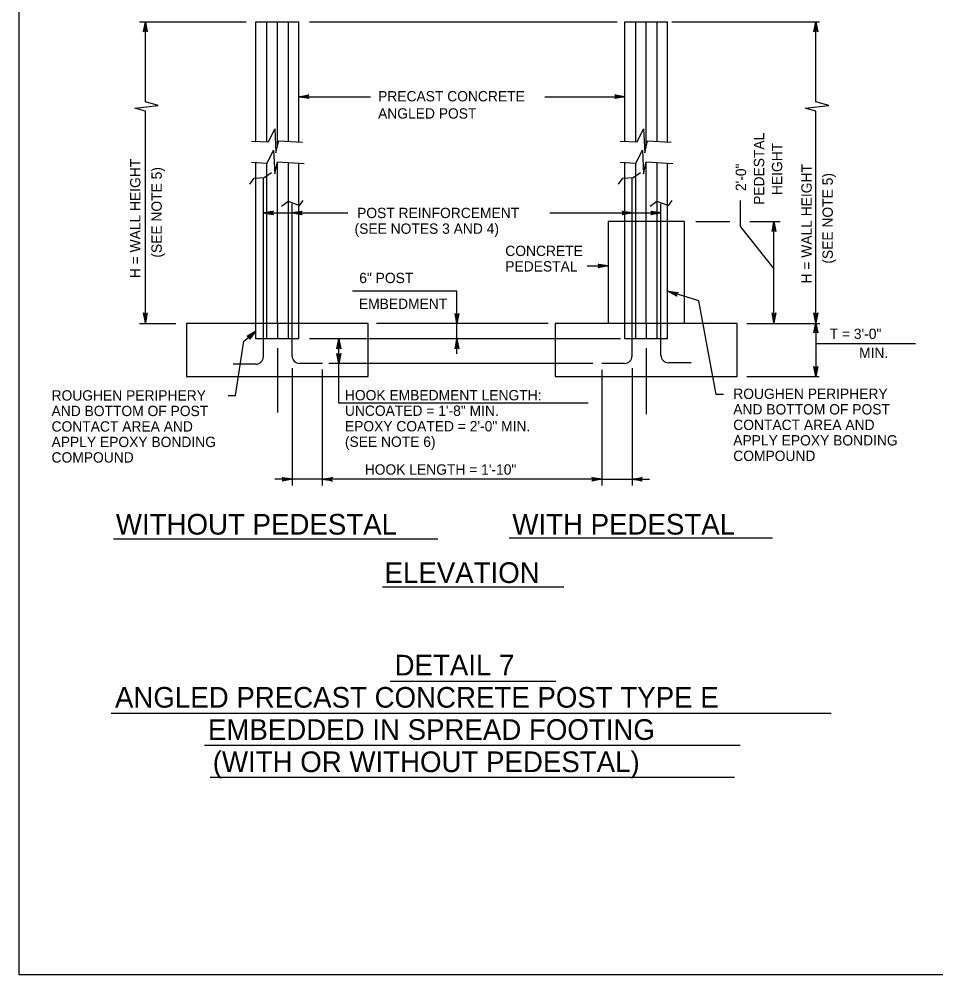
# Model space of a CAD drawing. Extents: x 3351 to 8430, y -3586 to 1457.
# Drawn here: x 5483.3 to 5755.8, y -2977.3 to -2693.1 of the extents above; entities that cross this region are included whole.
import ezdxf

# ---------------------------------------------------------------- set-up
doc = ezdxf.new("R2010")
doc.units = 0
doc.layers.add('1', color=7, linetype='Continuous')
doc.layers.add('2', color=7, linetype='Continuous')

msp = doc.modelspace()

# ---------------------------------------------------------------- linework, layer by layer
at = {"layer": '1'}
for p, q in [((5519.11, -2693.93), (5550.81, -2693.93)), ((5520.86, -2717.76), (5520.86, -2693.93)), ((5553.72, -2693.93), (5566.47, -2693.93)), ((5553.72, -2729.47), (5553.72, -2693.93)), ((5556.89, -2693.93), (5556.89, -2729.62)), ((5560.09, -2731.02), (5560.09, -2693.93)), ((5563.29, -2693.93), (5563.29, -2729.48)), ((5566.47, -2729.66), (5566.47, -2693.93)), ((5569.62, -2693.93), (5661.03, -2693.93)), ((5663.31, -2693.93), (5676.06, -2693.93)), ((5663.31, -2729.46), (5663.31, -2693.93)), ((5666.49, -2693.93), (5666.49, -2729.62)), ((5669.69, -2731.02), (5669.69, -2693.93)), ((5672.89, -2693.93), (5672.89, -2729.48)), ((5676.06, -2729.66), (5676.06, -2693.93)), ((5677.32, -2693.93), (5721.19, -2693.93)), ((5720.1, -2717.76), (5720.1, -2693.93)), ((5566.47, -2716.2), (5587.76, -2716.2)), ((5639.6, -2716.2), (5663.31, -2716.2)), ((5520.86, -2783.47), (5520.86, -2720.46)), ((5720.1, -2783.47), (5720.1, -2720.46)), ((5553.72, -2783.66), (5553.72, -2735.78)), ((5556.89, -2735.94), (5556.89, -2788.16)), ((5560.09, -2783.66), (5560.09, -2735.72)), ((5563.29, -2735.8), (5563.29, -2788.16)), ((5566.47, -2783.66), (5566.47, -2735.97)), ((5663.31, -2753.31), (5663.31, -2735.78)), ((5666.49, -2735.94), (5666.49, -2788.16)), ((5669.69, -2783.66), (5669.69, -2735.72)), ((5672.89, -2735.8), (5672.89, -2788.16)), ((5676.06, -2753.31), (5676.06, -2735.97)), ((5556.2, -2740.26), (5558.36, -2738.75)), ((5665.8, -2740.26), (5667.96, -2738.75)), ((5551.89, -2742.2), (5553.18, -2740.47)), ((5553.18, -2740.47), (5556.2, -2740.26)), ((5555.92, -2793.49), (5555.92, -2740.26)), ((5661.49, -2742.2), (5662.78, -2740.47)), ((5662.78, -2740.47), (5665.8, -2740.26)), ((5665.52, -2793.27), (5665.52, -2740.26)), ((5561.31, -2748.78), (5563.25, -2747.27)), ((5563.25, -2747.27), (5566.7, -2748.56)), ((5566.7, -2748.56), (5567.78, -2747.05)), ((5670.9, -2748.78), (5672.85, -2747.27)), ((5672.85, -2747.27), (5676.3, -2748.56)), ((5676.3, -2748.56), (5677.37, -2747.05)), ((5697.74, -2754.9), (5697.74, -2747.02)), ((5564.46, -2793.27), (5564.46, -2748.03)), ((5674.06, -2793.06), (5674.06, -2748.03)), ((5555.92, -2750.78), (5581.07, -2750.78)), ((5641.09, -2750.78), (5674.06, -2750.78)), ((5658.39, -2753.31), (5658.39, -2783.66)), ((5680.99, -2753.31), (5658.39, -2753.31)), ((5663.31, -2788.16), (5663.31, -2753.31)), ((5676.06, -2788.16), (5676.06, -2753.31)), ((5680.99, -2753.31), (5680.99, -2783.66)), ((5684.43, -2753.31), (5694.59, -2753.31)), ((5700.5, -2753.31), (5709.54, -2753.31)), ((5707.65, -2783.47), (5707.65, -2753.31)), ((5697.74, -2754.9), (5707.65, -2767.42)), ((5652.11, -2766.54), (5658.39, -2766.54)), ((5582.42, -2773.91), (5613.44, -2773.91)), ((5613.44, -2783.66), (5613.44, -2773.91)), ((5519.11, -2783.66), (5529.87, -2783.66)), ((5566.86, -2783.66), (5533.09, -2783.66)), ((5533.09, -2783.66), (5533.09, -2799.41)), ((5553.72, -2788.16), (5553.72, -2783.66)), ((5560.09, -2783.66), (5560.09, -2788.16)), ((5566.47, -2788.16), (5566.47, -2783.66)), ((5587.09, -2783.66), (5566.47, -2783.66)), ((5587.09, -2799.41), (5587.09, -2783.66)), ((5640.56, -2783.66), (5589.57, -2783.66)), ((5613.44, -2787.8), (5613.44, -2783.66)), ((5676.45, -2783.66), (5642.69, -2783.66)), ((5642.69, -2783.66), (5642.69, -2799.41)), ((5669.69, -2783.66), (5669.69, -2788.16)), ((5696.69, -2783.66), (5676.06, -2783.66)), ((5696.69, -2799.41), (5696.69, -2783.66)), ((5699.57, -2783.66), (5721.3, -2783.66)), ((5720.1, -2783.47), (5720.1, -2799.41)), ((5566.47, -2788.16), (5553.72, -2788.16)), ((5662.02, -2788.16), (5569.62, -2788.16)), ((5578.36, -2795.62), (5578.36, -2788.08)), ((5613.44, -2792.63), (5613.44, -2787.8)), ((5676.06, -2788.16), (5663.31, -2788.16)), ((5720.1, -2789.59), (5749.7, -2789.59)), ((5560.09, -2791), (5560.09, -2810.13)), ((5669.69, -2791), (5669.69, -2810.61)), ((5553.67, -2795.74), (5546.92, -2795.74)), ((5573.46, -2795.52), (5566.71, -2795.52)), ((5653.81, -2795.52), (5575.39, -2795.52)), ((5578.36, -2807.31), (5578.36, -2795.62)), ((5663.27, -2795.52), (5656.52, -2795.52)), ((5683.06, -2795.31), (5676.31, -2795.31)), ((5564.46, -2796.92), (5564.46, -2831.79)), ((5573.44, -2797.35), (5573.44, -2831.79)), ((5656.53, -2797.45), (5656.53, -2831.79)), ((5665.52, -2796.92), (5665.52, -2831.79)), ((5533.09, -2799.41), (5587.09, -2799.41)), ((5642.69, -2799.41), (5696.69, -2799.41)), ((5699.57, -2799.41), (5721.1, -2799.41)), ((5652.48, -2807.31), (5578.36, -2807.31)), ((5573.44, -2829.94), (5559.3, -2829.94)), ((5656.53, -2829.94), (5573.44, -2829.94)), ((5656.53, -2829.94), (5670.68, -2829.94)), ((5628.93, -2847.35), (5707.19, -2847.35)), ((5511.41, -2847.68), (5607.75, -2847.68)), ((5591.34, -2861.96), (5645.23, -2861.96)), ((5593.57, -2889.96), (5642.85, -2889.96)), ((5510.73, -2899.47), (5724.66, -2899.47)), ((5538.48, -2908.98), (5697.63, -2908.98)), ((5540.14, -2918.49), (5695.97, -2918.49))]:
    msp.add_line(p, q, dxfattribs=at)
for points in [[(5520.86, -2693.93), (5521.42, -2696.91), (5521.26, -2696.68), (5521.06, -2696.57), (5520.86, -2696.53), (5520.66, -2696.57), (5520.46, -2696.68), (5520.3, -2696.91), (5520.86, -2693.93), (5520.46, -2696.68), (5520.66, -2696.57), (5520.86, -2693.93), (5520.86, -2696.53), (5521.06, -2696.57), (5520.86, -2693.93), (5521.26, -2696.68)], [(5720.1, -2693.93), (5720.66, -2696.91), (5720.5, -2696.68), (5720.3, -2696.57), (5720.1, -2696.53), (5719.9, -2696.57), (5719.7, -2696.68), (5719.54, -2696.91), (5720.1, -2693.93), (5719.7, -2696.68), (5719.9, -2696.57), (5720.1, -2693.93), (5720.1, -2696.53), (5720.3, -2696.57), (5720.1, -2693.93), (5720.5, -2696.68)], [(5566.47, -2716.2), (5569.45, -2715.64), (5569.22, -2715.79), (5569.1, -2715.99), (5569.07, -2716.2), (5569.1, -2716.39), (5569.22, -2716.59), (5569.45, -2716.75), (5566.47, -2716.2), (5569.22, -2716.59), (5569.1, -2716.39), (5566.47, -2716.2), (5569.07, -2716.2), (5569.1, -2715.99), (5566.47, -2716.2), (5569.22, -2715.79)], [(5663.31, -2716.2), (5660.33, -2716.75), (5660.56, -2716.59), (5660.68, -2716.39), (5660.71, -2716.2), (5660.68, -2715.99), (5660.56, -2715.79), (5660.33, -2715.64), (5663.31, -2716.2), (5660.56, -2715.79), (5660.68, -2715.99), (5663.31, -2716.2), (5660.71, -2716.2), (5660.68, -2716.39), (5663.31, -2716.2), (5660.56, -2716.59)], [(5520.86, -2720.46), (5517.72, -2719.59), (5524.7, -2718.84), (5520.86, -2717.76)], [(5720.1, -2720.46), (5716.96, -2719.59), (5723.94, -2718.84), (5720.1, -2717.76)], [(5552.38, -2729.4), (5557.41, -2729.65), (5559.35, -2725.78), (5559.67, -2732.88), (5560.48, -2729.33), (5567.52, -2729.72)], [(5661.97, -2729.4), (5667.01, -2729.65), (5668.94, -2725.78), (5669.27, -2732.88), (5670.07, -2729.33), (5677.11, -2729.72)], [(5552.37, -2735.71), (5557.05, -2735.94), (5558.98, -2732.07), (5559.31, -2739.17), (5560.11, -2735.62), (5568.02, -2736.06)], [(5661.97, -2735.71), (5666.64, -2735.94), (5668.58, -2732.07), (5668.9, -2739.17), (5669.71, -2735.62), (5677.61, -2736.06)], [(5555.92, -2750.78), (5558.9, -2750.22), (5558.79, -2750.3), (5558.67, -2750.38), (5558.61, -2750.48), (5558.55, -2750.58), (5558.54, -2750.68), (5558.52, -2750.78), (5558.54, -2750.88), (5558.55, -2750.98), (5558.61, -2751.08), (5558.67, -2751.18), (5558.79, -2751.26), (5558.9, -2751.34), (5555.92, -2750.78), (5558.79, -2751.26), (5558.67, -2751.18), (5555.92, -2750.78), (5558.61, -2751.08), (5558.55, -2750.98), (5555.92, -2750.78), (5558.54, -2750.88), (5558.52, -2750.78), (5555.92, -2750.78), (5558.54, -2750.68), (5558.55, -2750.58), (5555.92, -2750.78), (5558.61, -2750.48), (5558.67, -2750.38), (5555.92, -2750.78), (5558.79, -2750.3)], [(5564.46, -2750.78), (5567.44, -2750.22), (5567.33, -2750.3), (5567.21, -2750.38), (5567.15, -2750.48), (5567.09, -2750.58), (5567.08, -2750.68), (5567.06, -2750.78), (5567.08, -2750.88), (5567.09, -2750.98), (5567.15, -2751.08), (5567.21, -2751.18), (5567.33, -2751.26), (5567.44, -2751.34), (5564.46, -2750.78), (5567.33, -2751.26), (5567.21, -2751.18), (5564.46, -2750.78), (5567.15, -2751.08), (5567.09, -2750.98), (5564.46, -2750.78), (5567.08, -2750.88), (5567.06, -2750.78), (5564.46, -2750.78), (5567.08, -2750.68), (5567.09, -2750.58), (5564.46, -2750.78), (5567.15, -2750.48), (5567.21, -2750.38), (5564.46, -2750.78), (5567.33, -2750.3)], [(5665.52, -2750.78), (5662.53, -2751.34), (5662.65, -2751.26), (5662.76, -2751.18), (5662.82, -2751.08), (5662.88, -2750.98), (5662.9, -2750.88), (5662.92, -2750.78), (5662.9, -2750.68), (5662.88, -2750.58), (5662.82, -2750.48), (5662.76, -2750.38), (5662.65, -2750.3), (5662.53, -2750.22), (5665.52, -2750.78), (5662.65, -2750.3), (5662.76, -2750.38), (5665.52, -2750.78), (5662.82, -2750.48), (5662.88, -2750.58), (5665.52, -2750.78), (5662.9, -2750.68), (5662.92, -2750.78), (5665.52, -2750.78), (5662.9, -2750.88), (5662.88, -2750.98), (5665.52, -2750.78), (5662.82, -2751.08), (5662.76, -2751.18), (5665.52, -2750.78), (5662.65, -2751.26)], [(5674.06, -2750.78), (5671.07, -2751.34), (5671.19, -2751.26), (5671.3, -2751.18), (5671.36, -2751.08), (5671.42, -2750.98), (5671.44, -2750.88), (5671.46, -2750.78), (5671.44, -2750.68), (5671.42, -2750.58), (5671.36, -2750.48), (5671.3, -2750.38), (5671.19, -2750.3), (5671.07, -2750.22), (5674.06, -2750.78), (5671.19, -2750.3), (5671.3, -2750.38), (5674.06, -2750.78), (5671.36, -2750.48), (5671.42, -2750.58), (5674.06, -2750.78), (5671.44, -2750.68), (5671.46, -2750.78), (5674.06, -2750.78), (5671.44, -2750.88), (5671.42, -2750.98), (5674.06, -2750.78), (5671.36, -2751.08), (5671.3, -2751.18), (5674.06, -2750.78), (5671.19, -2751.26)], [(5707.65, -2753.31), (5708.21, -2756.29), (5708.05, -2756.06), (5707.85, -2755.94), (5707.65, -2755.91), (5707.45, -2755.94), (5707.25, -2756.06), (5707.09, -2756.29), (5707.65, -2753.31), (5707.25, -2756.06), (5707.45, -2755.94), (5707.65, -2753.31), (5707.65, -2755.91), (5707.85, -2755.94), (5707.65, -2753.31), (5708.05, -2756.06)], [(5658.39, -2766.54), (5655.41, -2767.1), (5655.64, -2766.94), (5655.75, -2766.74), (5655.79, -2766.54), (5655.75, -2766.34), (5655.64, -2766.14), (5655.41, -2765.98), (5658.39, -2766.54), (5655.64, -2766.14), (5655.75, -2766.34), (5658.39, -2766.54), (5655.79, -2766.54), (5655.75, -2766.74), (5658.39, -2766.54), (5655.64, -2766.94)], [(5692.65, -2804.78), (5690.46, -2804.78), (5685.34, -2776.93), (5676.17, -2774.07)], [(5676.17, -2774.07), (5679.18, -2774.42), (5678.92, -2774.51), (5678.74, -2774.66), (5678.65, -2774.84), (5678.62, -2775.05), (5678.68, -2775.27), (5678.85, -2775.49), (5676.17, -2774.07), (5678.68, -2775.27), (5678.62, -2775.05), (5676.17, -2774.07), (5678.65, -2774.84), (5678.74, -2774.66), (5676.17, -2774.07), (5678.92, -2774.51)], [(5520.86, -2783.47), (5520.3, -2780.48), (5520.46, -2780.71), (5520.66, -2780.83), (5520.86, -2780.87), (5521.06, -2780.83), (5521.26, -2780.71), (5521.42, -2780.48), (5520.86, -2783.47), (5521.26, -2780.71), (5521.06, -2780.83), (5520.86, -2783.47), (5520.86, -2780.87), (5520.66, -2780.83), (5520.86, -2783.47), (5520.46, -2780.71)], [(5613.44, -2783.66), (5612.88, -2780.67), (5613.04, -2780.9), (5613.24, -2781.02), (5613.44, -2781.06), (5613.64, -2781.02), (5613.84, -2780.9), (5614, -2780.67), (5613.44, -2783.66), (5613.84, -2780.9), (5613.64, -2781.02), (5613.44, -2783.66), (5613.44, -2781.06), (5613.24, -2781.02), (5613.44, -2783.66), (5613.04, -2780.9)], [(5707.65, -2783.47), (5707.09, -2780.48), (5707.25, -2780.71), (5707.45, -2780.83), (5707.65, -2780.87), (5707.85, -2780.83), (5708.05, -2780.71), (5708.21, -2780.48), (5707.65, -2783.47), (5708.05, -2780.71), (5707.85, -2780.83), (5707.65, -2783.47), (5707.65, -2780.87), (5707.45, -2780.83), (5707.65, -2783.47), (5707.25, -2780.71)], [(5720.1, -2783.47), (5719.54, -2780.48), (5719.7, -2780.71), (5719.9, -2780.83), (5720.1, -2780.87), (5720.3, -2780.83), (5720.5, -2780.71), (5720.66, -2780.48), (5720.1, -2783.47), (5720.5, -2780.71), (5720.3, -2780.83), (5720.1, -2783.47), (5720.1, -2780.87), (5719.9, -2780.83), (5720.1, -2783.47), (5719.7, -2780.71)], [(5720.1, -2783.47), (5720.66, -2786.45), (5720.5, -2786.22), (5720.3, -2786.1), (5720.1, -2786.07), (5719.9, -2786.1), (5719.7, -2786.22), (5719.54, -2786.45), (5720.1, -2783.47), (5719.7, -2786.22), (5719.9, -2786.1), (5720.1, -2783.47), (5720.1, -2786.07), (5720.3, -2786.1), (5720.1, -2783.47), (5720.5, -2786.22)], [(5545.44, -2805.03), (5547.63, -2805.03), (5550.12, -2788.91), (5553.72, -2785.91)], [(5553.72, -2785.91), (5551.79, -2788.25), (5551.82, -2788.11), (5551.86, -2787.98), (5551.84, -2787.86), (5551.82, -2787.75), (5551.77, -2787.66), (5551.72, -2787.57), (5551.64, -2787.51), (5551.57, -2787.44), (5551.46, -2787.4), (5551.35, -2787.36), (5551.21, -2787.38), (5551.07, -2787.39), (5553.72, -2785.91), (5551.21, -2787.38), (5551.35, -2787.36), (5553.72, -2785.91), (5551.46, -2787.4), (5551.57, -2787.44), (5553.72, -2785.91), (5551.64, -2787.51), (5551.72, -2787.57), (5553.72, -2785.91), (5551.77, -2787.66), (5551.82, -2787.75), (5553.72, -2785.91), (5551.84, -2787.86), (5551.86, -2787.98), (5553.72, -2785.91), (5551.82, -2788.11)], [(5578.36, -2788.16), (5578.92, -2791.14), (5578.76, -2790.91), (5578.56, -2790.79), (5578.36, -2790.76), (5578.16, -2790.79), (5577.96, -2790.91), (5577.8, -2791.14), (5578.36, -2788.16), (5577.96, -2790.91), (5578.16, -2790.79), (5578.36, -2788.16), (5578.36, -2790.76), (5578.56, -2790.79), (5578.36, -2788.16), (5578.76, -2790.91)], [(5613.44, -2788.16), (5614, -2791.14), (5613.84, -2790.91), (5613.64, -2790.79), (5613.44, -2790.76), (5613.24, -2790.79), (5613.04, -2790.91), (5612.88, -2791.14), (5613.44, -2788.16), (5613.04, -2790.91), (5613.24, -2790.79), (5613.44, -2788.16), (5613.44, -2790.76), (5613.64, -2790.79), (5613.44, -2788.16), (5613.84, -2790.91)], [(5578.36, -2795.52), (5577.8, -2792.54), (5577.96, -2792.77), (5578.16, -2792.89), (5578.36, -2792.92), (5578.56, -2792.89), (5578.76, -2792.77), (5578.92, -2792.54), (5578.36, -2795.52), (5578.76, -2792.77), (5578.56, -2792.89), (5578.36, -2795.52), (5578.36, -2792.92), (5578.16, -2792.89), (5578.36, -2795.52), (5577.96, -2792.77)], [(5720.1, -2799.41), (5719.54, -2796.42), (5719.7, -2796.65), (5719.9, -2796.77), (5720.1, -2796.81), (5720.3, -2796.77), (5720.5, -2796.65), (5720.66, -2796.42), (5720.1, -2799.41), (5720.5, -2796.65), (5720.3, -2796.77), (5720.1, -2799.41), (5720.1, -2796.81), (5719.9, -2796.77), (5720.1, -2799.41), (5719.7, -2796.65)], [(5564.46, -2829.94), (5561.48, -2830.5), (5561.71, -2830.34), (5561.83, -2830.14), (5561.86, -2829.94), (5561.83, -2829.74), (5561.71, -2829.54), (5561.48, -2829.38), (5564.46, -2829.94), (5561.71, -2829.54), (5561.83, -2829.74), (5564.46, -2829.94), (5561.86, -2829.94), (5561.83, -2830.14), (5564.46, -2829.94), (5561.71, -2830.34)], [(5573.44, -2829.94), (5576.43, -2829.38), (5576.2, -2829.54), (5576.08, -2829.74), (5576.04, -2829.94), (5576.08, -2830.14), (5576.2, -2830.34), (5576.43, -2830.5), (5573.44, -2829.94), (5576.2, -2830.34), (5576.08, -2830.14), (5573.44, -2829.94), (5576.04, -2829.94), (5576.08, -2829.74), (5573.44, -2829.94), (5576.2, -2829.54)], [(5656.53, -2829.94), (5653.55, -2830.5), (5653.78, -2830.34), (5653.9, -2830.14), (5653.93, -2829.94), (5653.9, -2829.74), (5653.78, -2829.54), (5653.55, -2829.38), (5656.53, -2829.94), (5653.78, -2829.54), (5653.9, -2829.74), (5656.53, -2829.94), (5653.93, -2829.94), (5653.9, -2830.14), (5656.53, -2829.94), (5653.78, -2830.34)], [(5665.52, -2829.94), (5668.5, -2829.38), (5668.27, -2829.54), (5668.15, -2829.74), (5668.12, -2829.94), (5668.15, -2830.14), (5668.27, -2830.34), (5668.5, -2830.5), (5665.52, -2829.94), (5668.27, -2830.34), (5668.15, -2830.14), (5665.52, -2829.94), (5668.12, -2829.94), (5668.15, -2829.74), (5665.52, -2829.94), (5668.27, -2829.54)]]:
    msp.add_lwpolyline(points, dxfattribs=at)
for centre, start, end in [((5566.71, -2793.27), 180, 270), ((5663.27, -2793.27), 270, 360), ((5676.31, -2793.06), 180, 270), ((5553.67, -2793.49), 270, 360)]:
    msp.add_arc(centre, 2.25, start, end, dxfattribs=at)
at = {"layer": '2'}
for p, q in [((5483.34, -2977.31), (5483.34, -2413.31)), ((6269.34, -2977.31), (5483.34, -2977.31))]:
    msp.add_line(p, q, dxfattribs=at)

# ---------------------------------------------------------------- texts
at = {"layer": '1'}
for s, height, p in [('PRECAST CONCRETE', 3.072, (5590.02, -2717.6)), ('ANGLED POST', 3.072, (5590.02, -2722.72)), ('POST REINFORCEMENT', 3.072, (5583.79, -2752.3)), ('(SEE NOTES 3 AND 4)', 3.072, (5583.03, -2756.97)), ('CONCRETE', 3.072, (5627.82, -2763.58)), ('PEDESTAL', 3.072, (5627.82, -2768.18)), ('6" POST', 3.072, (5584.42, -2771.63)), ('EMBEDMENT', 3.072, (5584.32, -2779.33)), ('T = 3\'-0"', 3.072, (5724.22, -2788.24)), ('MIN.', 3.072, (5732.97, -2793.87)), ('ROUGHEN PERIPHERY', 3.072, (5492.98, -2806.56)), ('HOOK EMBEDMENT LENGTH:', 3.072, (5580.16, -2806.49)), ('ROUGHEN PERIPHERY', 3.072, (5695.57, -2806.08)), ('AND BOTTOM OF POST', 3.072, (5695.57, -2810.69)), ('AND BOTTOM OF POST', 3.072, (5492.98, -2811.17)), ('UNCOATED = 1\'-8" MIN.', 3.072, (5580.16, -2811.1)), ('CONTACT AREA AND', 3.072, (5492.98, -2815.78)), ('EPOXY COATED = 2\'-0" MIN.', 3.072, (5580.16, -2815.71)), ('CONTACT AREA AND', 3.072, (5695.57, -2815.3)), ('APPLY EPOXY BONDING', 3.072, (5492.98, -2820.38)), ('(SEE NOTE 6)', 3.072, (5580.16, -2820.32)), ('APPLY EPOXY BONDING', 3.072, (5695.57, -2819.91)), ('COMPOUND', 3.072, (5695.57, -2824.52)), ('COMPOUND', 3.072, (5492.98, -2824.99)), ('HOOK LENGTH = 1\'-10"', 3.072, (5586.06, -2828.58)), ('WITHOUT PEDESTAL', 6.1439, (5512.1, -2846.4)), ('WITH PEDESTAL', 6.1439, (5629.92, -2846.4)), ('ELEVATION', 6.144, (5591.93, -2860.79)), ('DETAIL 7', 6.144, (5594.92, -2888.28)), ('ANGLED PRECAST CONCRETE POST TYPE E', 6.1439, (5511.83, -2897.86)), ('EMBEDDED IN SPREAD FOOTING', 6.1439, (5539.45, -2907.44)), ('(WITH OR WITHOUT PEDESTAL)', 6.1439, (5540.88, -2917.02))]:
    msp.add_text(s, height=height, dxfattribs=at).set_placement(p)
for s, p in [('PEDESTAL', (5704.76, -2748.37)), ('HEIGHT', (5710.13, -2745.45)), ('H = WALL HEIGHT', (5519.39, -2770.16)), ('2\'-0"', (5699.38, -2744.27)), ('H = WALL HEIGHT', (5718.89, -2771.74)), ('(SEE NOTE 5)', (5525.74, -2764.06)), ('(SEE NOTE 5)', (5725.16, -2765.84))]:
    msp.add_text(s, height=3.072, rotation=90, dxfattribs=at).set_placement(p)

doc.saveas('drawing.dxf')
